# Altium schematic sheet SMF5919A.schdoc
size 127 x 101 mm
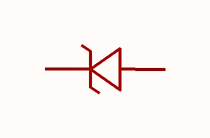
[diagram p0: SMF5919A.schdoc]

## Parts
D?  smf5919a  [SOD-123FL_L2.8-W1.9-LS3.7-RD]  (value not drawn)

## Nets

Not connected (* = marked no-connect by the designer): D? 1(K) 2(A)

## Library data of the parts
D? = smf5919a: 二极管配置:1个独立式;稳压值(标称值):5.6V;稳压值(范围值):5.32V~5.88V;耗散功率(Pd):1.5W;; Manufacturer: CJ(江苏长电/长晶); AddInBom: yes; ModelId: ee80cc4b5e2f4a0b8a944bbfc66c96ba; ModelTransform: 141.732,74.803,0,0,0,0,0,0,0; Diode Configuration: 1个独立式; Zener Voltage(Nom): 5.6V; Reverse Leakage Current (Ir): 5uA@3V; Pd - Power Dissipation: 1.5W; Impedance(Zzt): 2Ω; Impedance(Zzk): 250Ω; Operating Junction Temperature Range: -55℃~+150℃; Tolerance: ±5%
